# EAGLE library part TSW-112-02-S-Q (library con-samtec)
THROUGH-HOLE .025" SQ POST HEADER Source: Samtec TSW.pdf
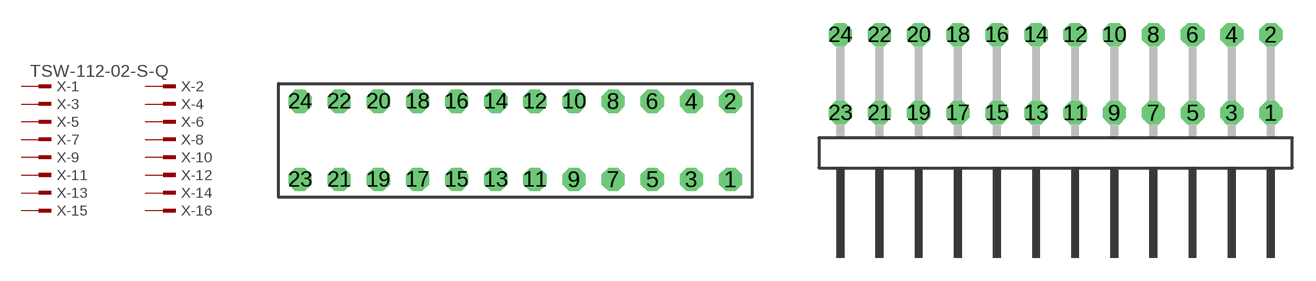
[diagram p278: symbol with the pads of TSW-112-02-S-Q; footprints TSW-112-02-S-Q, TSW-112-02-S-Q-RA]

Designator prefix X; gates -1=MPINV -2=MPIN -3=MPIN -4=MPIN -5=MPIN -6=MPIN -7=MPIN -8=MPIN -9=MPIN -10=MPIN -11=MPIN -12=MPIN -13=MPIN -14=MPIN -15=MPIN -16=MPIN -17=MPIN -18=MPIN -19=MPIN -20=MPIN -21=MPIN -22=MPIN -23=MPIN -24=MPIN

## TSW-112-02-S-Q (OC_FARNELL: unknown; OC_NEWARK: unknown)  [TSW-112-02-S-Q]
1  -1:1  pas
2  -2:1  pas
3  -3:1  pas
4  -4:1  pas
5  -5:1  pas
6  -6:1  pas
7  -7:1  pas
8  -8:1  pas
9  -9:1  pas
10  -10:1  pas
11  -11:1  pas
12  -12:1  pas
13  -13:1  pas
14  -14:1  pas
15  -15:1  pas
16  -16:1  pas
17  -17:1  pas
18  -18:1  pas
19  -19:1  pas
20  -20:1  pas
21  -21:1  pas
22  -22:1  pas
23  -23:1  pas
24  -24:1  pas

## TSW-112-02-S-Q-RA (OC_FARNELL: unknown; OC_NEWARK: unknown)  [TSW-112-02-S-Q-RA]
Pads as for TSW-112-02-S-Q

## Footprint TSW-112-02-S-Q (pad centres in mm)
THROUGH-HOLE .025" SQ POST HEADER Source: Samtec TSW.pdf
drill 1 pad 1.5 octagon: 1 13.97,-2.54; 2 13.97,2.54; 3 11.43,-2.54; 4 11.43,2.54; 5 8.89,-2.54; 6 8.89,2.54; 7 6.35,-2.54; 8 6.35,2.54; 9 3.81,-2.54; 10 3.81,2.54; 11 1.27,-2.54; 12 1.27,2.54; 13 -1.27,-2.54; 14 -1.27,2.54; 15 -3.81,-2.54; 16 -3.81,2.54; 17 -6.35,-2.54; 18 -6.35,2.54; 19 -8.89,-2.54; 20 -8.89,2.54; 21 -11.43,-2.54; 22 -11.43,2.54; 23 -13.97,-2.54; 24 -13.97,2.54

## Footprint TSW-112-02-S-Q-RA (pad centres in mm)
THROUGH-HOLE .025" SQ POST HEADER Source: Samtec TSW.pdf
drill 1 pad 1.5 octagon: 1 13.97,1.524; 2 13.97,6.604; 3 11.43,1.524; 4 11.43,6.604; 5 8.89,1.524; 6 8.89,6.604; 7 6.35,1.524; 8 6.35,6.604; 9 3.81,1.524; 10 3.81,6.604; 11 1.27,1.524; 12 1.27,6.604; 13 -1.27,1.524; 14 -1.27,6.604; 15 -3.81,1.524; 16 -3.81,6.604; 17 -6.35,1.524; 18 -6.35,6.604; 19 -8.89,1.524; 20 -8.89,6.604; 21 -11.43,1.524; 22 -11.43,6.604; 23 -13.97,1.524; 24 -13.97,6.604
